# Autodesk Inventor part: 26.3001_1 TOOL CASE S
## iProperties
Created: 2009-09
Part Number: 26.3001_1 TOOL CASE S
Material: Rubber
Document SubType Name: Modeling
Designer: Administrator
Mass: 457.442 g
Surface Area: 884.383 cm^2
Volume: 491.873 cm^3
Density: 0.93 g/cm^3
Author: Administrator
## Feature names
1. Base1
